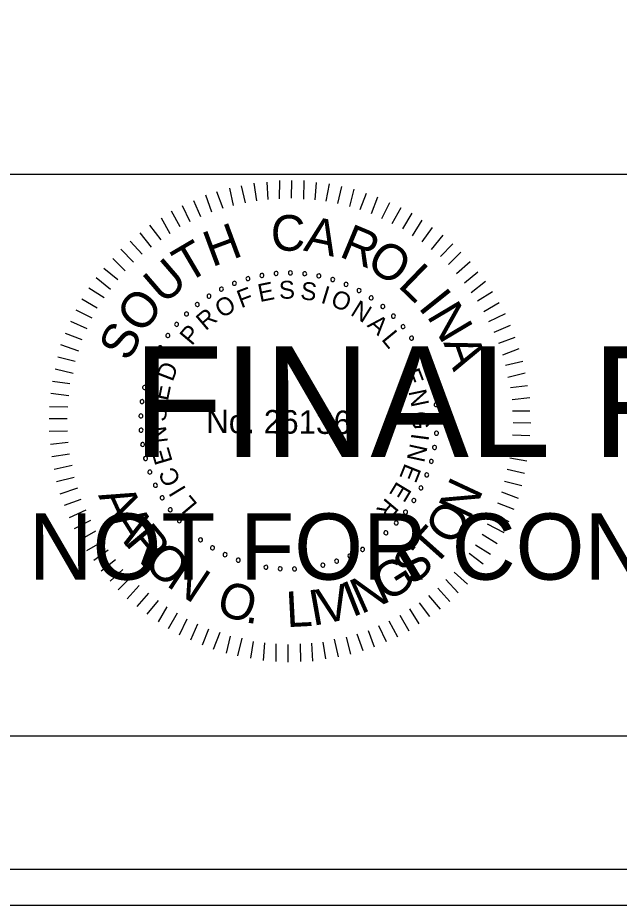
# Model space of a CAD drawing. Extents: x 967 to 1326, y 964 to 3704.
# Drawn here: x 1170.56 to 1189.3, y 963.72 to 991.36 of the extents above; entities that cross this region are included whole.
import ezdxf

# ---------------------------------------------------------------- set-up
doc = ezdxf.new("R2010")
doc.units = 0
for name, color, linetype in [('RD_SHT_Bndy', 7, 'Continuous'), ('RD_SHT_IplotShp', 7, 'Continuous'), ('RD_SHT_Misc1', 7, 'Continuous'), ('RD_SHT_Misc2', 7, 'Continuous'), ('RD_XS_TX_Station', 7, 'Continuous')]:
    doc.layers.add(name, color=color, linetype=linetype)

msp = doc.modelspace()

# ---------------------------------------------------------------- linework, layer by layer
at = {"layer": 'RD_SHT_Bndy'}
for p, q in [((996.114, 986.486), (1323.886, 986.486)), ((1323.886, 968.983), (996.114, 968.983))]:
    msp.add_line(p, q, dxfattribs=at)
at = {"layer": 'RD_SHT_IplotShp'}
for points in [[(967.409, 963.72), (1326.285, 963.72), (1326.285, 1183.72), (967.409, 1183.72)], [(988.525, 964.84), (1326.285, 964.84), (1326.285, 1182.6), (988.525, 1182.6)]]:
    msp.add_lwpolyline(points, close=True, dxfattribs=at)
at = {"layer": 'RD_SHT_Misc1'}
for p, q in [((1178.01, 985.663), (1177.93, 986.209)), ((1178.364, 985.699), (1178.33, 986.244)), ((1178.717, 985.719), (1178.722, 986.295)), ((1179.093, 985.739), (1179.098, 986.292)), ((1179.469, 985.713), (1179.489, 986.288)), ((1179.829, 985.687), (1179.872, 986.231)), ((1180.174, 985.646), (1180.271, 986.19)), ((1176.964, 985.419), (1176.769, 985.935)), ((1177.287, 985.508), (1177.169, 986.054)), ((1177.657, 985.597), (1177.53, 986.128)), ((1180.535, 985.573), (1180.662, 986.102)), ((1180.902, 985.478), (1181.045, 986.022)), ((1176.264, 985.156), (1176.053, 985.657)), ((1176.61, 985.306), (1176.423, 985.83)), ((1181.231, 985.384), (1181.428, 985.896)), ((1181.584, 985.265), (1181.78, 985.786)), ((1175.933, 985.005), (1175.699, 985.506)), ((1181.905, 985.109), (1182.154, 985.606)), ((1182.226, 984.953), (1182.506, 985.45)), ((1175.308, 984.634), (1175.036, 985.12)), ((1175.624, 984.846), (1175.352, 985.332)), ((1182.562, 984.789), (1182.85, 985.27)), ((1175.03, 984.445), (1174.681, 984.9)), ((1182.86, 984.572), (1183.163, 985.053)), ((1183.158, 984.378), (1183.484, 984.828)), ((1174.729, 984.217), (1174.372, 984.665)), ((1183.447, 984.145), (1183.811, 984.587)), ((1174.435, 983.997), (1174.062, 984.399)), ((1183.729, 983.92), (1184.116, 984.316)), ((1174.172, 983.753), (1173.776, 984.148)), ((1183.98, 983.672), (1184.368, 984.061)), ((1173.909, 983.479), (1173.52, 983.858)), ((1184.232, 983.394), (1184.657, 983.767)), ((1173.684, 983.197), (1173.242, 983.546)), ((1184.475, 983.108), (1184.892, 983.45)), ((1173.451, 982.9), (1173.009, 983.256)), ((1184.687, 982.807), (1185.128, 983.156)), ((1173.257, 982.64), (1172.776, 982.936)), ((1173.039, 982.312), (1172.559, 982.6)), ((1184.885, 982.544), (1185.355, 982.832)), ((1185.081, 982.213), (1185.56, 982.493)), ((1172.883, 982.006), (1172.379, 982.256)), ((1185.24, 981.904), (1185.756, 982.145)), ((1172.727, 981.677), (1172.215, 981.904)), ((1185.399, 981.573), (1185.907, 981.791)), ((1172.571, 981.333), (1172.051, 981.53)), ((1185.549, 981.226), (1186.057, 981.414)), ((1172.461, 980.974), (1171.91, 981.178)), ((1185.669, 980.865), (1186.185, 981.06)), ((1172.351, 980.652), (1171.807, 980.787)), ((1185.759, 980.541), (1186.297, 980.667)), ((1172.286, 980.276), (1171.727, 980.419)), ((1185.832, 980.165), (1186.371, 980.298)), ((1172.191, 979.955), (1171.647, 980.029)), ((1185.906, 979.842), (1186.436, 979.906)), ((1172.15, 979.587), (1171.598, 979.653)), ((1185.964, 979.473), (1186.51, 979.53)), ((1172.124, 979.234), (1171.548, 979.239)), ((1185.977, 979.12), (1186.514, 979.115)), ((1172.105, 978.866), (1171.545, 978.871)), ((1185.997, 978.751), (1186.542, 978.747)), ((1172.118, 978.482), (1171.542, 978.471)), ((1185.971, 978.368), (1186.508, 978.348)), ((1172.138, 978.136), (1171.585, 978.072)), ((1185.952, 978.022), (1186.497, 977.949)), ((1172.173, 977.768), (1171.627, 977.688)), ((1185.888, 977.655), (1186.417, 977.566)), ((1172.262, 977.414), (1171.701, 977.296)), ((1185.808, 977.302), (1186.345, 977.175)), ((1172.321, 977.037), (1171.774, 976.911)), ((1185.729, 976.926), (1186.265, 976.792)), ((1172.425, 976.707), (1171.871, 976.519)), ((1185.634, 976.597), (1186.146, 976.401)), ((1172.53, 976.36), (1172.007, 976.173)), ((1185.508, 976.253), (1186.013, 976.057)), ((1172.681, 976.029), (1172.165, 975.788)), ((1172.831, 975.705), (1172.323, 975.441)), ((1185.352, 975.924), (1185.857, 975.675)), ((1185.188, 975.603), (1185.7, 975.33)), ((1172.982, 975.374), (1172.497, 975.094)), ((1185.024, 975.274), (1185.498, 974.987)), ((1173.194, 975.042), (1172.709, 974.762)), ((1184.822, 974.946), (1185.288, 974.658)), ((1173.384, 974.78), (1172.936, 974.453)), ((1184.62, 974.687), (1185.055, 974.353)), ((1173.612, 974.478), (1173.164, 974.129)), ((1184.403, 974.389), (1184.814, 974.033)), ((1173.832, 974.177), (1173.437, 973.812)), ((1184.155, 974.092), (1184.574, 973.72)), ((1174.091, 973.945), (1173.689, 973.541)), ((1183.899, 973.864), (1184.28, 973.454)), ((1174.35, 973.674), (1173.97, 973.263)), ((1183.644, 973.597), (1184.024, 973.18)), ((1174.64, 973.442), (1174.275, 973.022)), ((1174.937, 973.209), (1174.58, 972.782)), ((1183.358, 973.37), (1183.715, 972.944)), ((1175.212, 973.014), (1174.932, 972.549)), ((1182.764, 972.952), (1183.059, 972.482)), ((1183.065, 973.141), (1183.384, 972.709)), ((1175.525, 972.812), (1175.245, 972.331)), ((1182.463, 972.755), (1182.743, 972.269)), ((1175.83, 972.633), (1175.588, 972.136)), ((1176.159, 972.477), (1175.94, 971.98)), ((1181.8, 972.431), (1182.041, 971.93)), ((1182.124, 972.581), (1182.396, 972.08)), ((1176.503, 972.321), (1176.307, 971.816)), ((1176.855, 972.211), (1176.651, 971.69)), ((1177.177, 972.1), (1177.05, 971.572)), ((1181.122, 972.175), (1181.31, 971.652)), ((1181.476, 972.28), (1181.664, 971.771)), ((1177.545, 972.036), (1177.409, 971.484)), ((1177.897, 971.933), (1177.808, 971.412)), ((1178.25, 971.892), (1178.207, 971.34)), ((1178.603, 971.866), (1178.598, 971.313)), ((1178.978, 971.84), (1178.974, 971.295)), ((1179.355, 971.86), (1179.365, 971.307)), ((1179.715, 971.88), (1179.749, 971.327)), ((1180.061, 971.915), (1180.149, 971.393)), ((1180.423, 972.012), (1180.541, 971.458)), ((1180.791, 972.07), (1180.926, 971.54))]:
    msp.add_line(p, q, dxfattribs=at)
for centre, start, end in [((1178.609, 983.397), 5.0653, 185.0653), ((1179.055, 983.414), 359.5268, 179.5268), ((1179.5, 983.388), 353.9884, 173.9884), ((1177.312, 983.091), 21.6807, 201.6807), ((1177.734, 983.235), 16.1422, 196.1422), ((1177.734, 983.235), 196.1422, 16.1422), ((1178.168, 983.337), 10.6038, 190.6038), ((1178.168, 983.337), 190.6038, 10.6038), ((1178.609, 983.397), 185.0653, 5.0653), ((1179.055, 983.414), 179.5268, 359.5268), ((1179.5, 983.388), 173.9884, 353.9884), ((1179.94, 983.319), 168.4499, 348.4499), ((1179.94, 983.319), 348.4499, 168.4499), ((1180.372, 983.208), 162.9114, 342.9114), ((1180.372, 983.208), 342.9114, 162.9114), ((1176.906, 982.908), 27.2191, 207.2191), ((1176.906, 982.908), 207.2191, 27.2191), ((1177.312, 983.091), 201.6807, 21.6807), ((1180.79, 983.056), 157.373, 337.373), ((1180.79, 983.056), 337.373, 157.373), ((1181.193, 982.864), 151.8345, 331.8345), ((1181.193, 982.864), 331.8345, 151.8345), ((1176.52, 982.686), 32.7576, 212.7576), ((1176.52, 982.686), 212.7576, 32.7576), ((1181.574, 982.634), 146.2961, 326.2961), ((1181.574, 982.634), 326.2961, 146.2961), ((1176.156, 982.428), 38.2961, 218.2961), ((1176.156, 982.428), 218.2961, 38.2961), ((1181.932, 982.368), 140.7576, 320.7576), ((1181.932, 982.368), 320.7576, 140.7576), ((1175.82, 982.135), 43.8345, 223.8345), ((1175.82, 982.135), 223.8345, 43.8345), ((1182.263, 982.069), 135.2191, 315.2191), ((1182.263, 982.069), 315.2191, 135.2191), ((1175.513, 981.812), 49.373, 229.373), ((1175.513, 981.812), 229.373, 49.373), ((1182.563, 981.74), 129.6807, 309.6807), ((1182.563, 981.74), 309.6807, 129.6807), ((1175.239, 981.461), 54.9114, 234.9114), ((1175.239, 981.461), 234.9114, 54.9114), ((1182.83, 981.383), 124.1422, 304.1422), ((1182.83, 981.383), 304.1422, 124.1422), ((1175, 981.085), 60.4499, 240.4499), ((1175, 981.085), 240.4499, 60.4499), ((1183.061, 981.002), 118.6038, 298.6038), ((1183.061, 981.002), 298.6038, 118.6038), ((1174.798, 980.687), 65.9884, 245.9884), ((1174.798, 980.687), 245.9884, 65.9884), ((1183.255, 980.601), 293.0653, 113.0653), ((1183.255, 980.601), 113.0653, 293.0653), ((1174.636, 980.272), 71.5268, 251.5268), ((1174.636, 980.272), 251.5268, 71.5268), ((1183.408, 980.182), 107.5268, 287.5268), ((1183.408, 980.182), 287.5268, 107.5268), ((1174.514, 979.843), 77.0653, 257.0653), ((1174.514, 979.843), 257.0653, 77.0653), ((1183.521, 979.751), 101.9884, 281.9884), ((1183.521, 979.751), 281.9884, 101.9884), ((1174.435, 979.405), 82.6038, 262.6038), ((1174.435, 979.405), 262.6038, 82.6038), ((1183.592, 979.311), 96.4499, 276.4499), ((1183.592, 979.311), 276.4499, 96.4499), ((1174.398, 978.961), 88.1422, 268.1422), ((1174.398, 978.961), 268.1422, 88.1422), ((1183.619, 978.866), 90.9114, 270.9114), ((1183.619, 978.866), 270.9114, 90.9114), ((1174.404, 978.515), 93.6807, 273.6807), ((1174.404, 978.515), 273.6807, 93.6807), ((1183.604, 978.421), 85.373, 265.373), ((1183.604, 978.421), 265.373, 85.373), ((1174.453, 978.072), 99.2191, 279.2191), ((1174.453, 978.072), 279.2191, 99.2191), ((1183.546, 977.979), 79.8345, 259.8345), ((1183.546, 977.979), 259.8345, 79.8345), ((1174.545, 977.636), 104.7576, 284.7576), ((1174.545, 977.636), 284.7576, 104.7576), ((1183.445, 977.545), 74.2961, 254.2961), ((1183.445, 977.545), 254.2961, 74.2961), ((1174.678, 977.211), 110.2961, 290.2961), ((1174.678, 977.211), 290.2961, 110.2961), ((1183.303, 977.122), 68.7576, 248.7576), ((1183.303, 977.122), 248.7576, 68.7576), ((1174.852, 976.8), 115.8345, 295.8345), ((1174.852, 976.8), 295.8345, 115.8345), ((1183.121, 976.716), 63.2191, 243.2191), ((1183.121, 976.716), 243.2191, 63.2191), ((1175.065, 976.409), 121.373, 301.373), ((1175.065, 976.409), 301.373, 121.373), ((1182.9, 976.328), 57.6807, 237.6807), ((1182.9, 976.328), 237.6807, 57.6807), ((1175.314, 976.039), 126.9114, 306.9114), ((1175.314, 976.039), 306.9114, 126.9114), ((1182.643, 975.964), 52.1422, 232.1422), ((1182.643, 975.964), 232.1422, 52.1422), ((1175.598, 975.696), 132.4499, 312.4499), ((1175.598, 975.696), 312.4499, 132.4499), ((1182.353, 975.627), 46.6038, 226.6038), ((1175.914, 975.381), 137.9884, 317.9884), ((1175.914, 975.381), 317.9884, 137.9884), ((1182.353, 975.627), 226.6038, 46.6038), ((1176.258, 975.099), 143.5268, 323.5268), ((1176.258, 975.099), 323.5268, 143.5268), ((1182.03, 975.319), 41.0653, 221.0653), ((1182.03, 975.319), 221.0653, 41.0653), ((1176.629, 974.851), 149.0653, 329.0653), ((1176.629, 974.851), 329.0653, 149.0653), ((1181.305, 974.803), 29.9884, 209.9884), ((1181.68, 975.043), 35.5268, 215.5268), ((1181.68, 975.043), 215.5268, 35.5268), ((1177.021, 974.639), 154.6038, 334.6038), ((1177.021, 974.639), 334.6038, 154.6038), ((1180.908, 974.6), 24.4499, 204.4499), ((1180.908, 974.6), 204.4499, 24.4499), ((1181.305, 974.803), 209.9884, 29.9884), ((1177.432, 974.467), 160.1422, 340.1422), ((1177.432, 974.467), 340.1422, 160.1422), ((1177.858, 974.335), 165.6807, 345.6807), ((1177.858, 974.335), 345.6807, 165.6807), ((1178.294, 974.245), 351.2191, 171.2191), ((1180.065, 974.313), 13.373, 193.373), ((1180.065, 974.313), 193.373, 13.373), ((1180.494, 974.436), 18.9114, 198.9114), ((1180.494, 974.436), 198.9114, 18.9114), ((1178.294, 974.245), 171.2191, 351.2191), ((1178.737, 974.198), 356.7576, 176.7576), ((1178.737, 974.198), 176.7576, 356.7576), ((1179.183, 974.193), 2.2961, 182.2961), ((1179.183, 974.193), 182.2961, 2.2961), ((1179.627, 974.232), 7.8345, 187.8345), ((1179.627, 974.232), 187.8345, 7.8345)]:
    msp.add_arc(centre, 0.0627, start, end, dxfattribs=at)
at = {"layer": 'RD_XS_TX_Station'}
msp.add_lwpolyline([(967.409, 963.72), (1326.285, 963.72), (1326.285, 1183.72), (967.409, 1183.72)], close=True, dxfattribs=at)

# ---------------------------------------------------------------- texts
at = {"layer": 'RD_SHT_Misc1'}
for s, height, rotation, p in [('C', 1.11, 359.5482, (1178.442, 984.108)), ('A', 1.11, 348.1981, (1179.439, 984.115)), ('H', 1.11, 20.3637, (1176.614, 983.587)), ('R', 1.11, 337.4344, (1180.541, 983.937)), ('T', 1.11, 30.4992, (1175.828, 983.072)), ('O', 1.108, 326.5869, (1181.366, 983.609)), ('U', 1.11, 40.8022, (1175.102, 982.403)), ('L', 1.11, 315.9488, (1182.373, 983.003)), ('S', 0.557, 2.208, (1178.709, 982.601)), ('F', 0.557, 20.6127, (1177.52, 982.309)), ('E', 0.557, 11.4103, (1178.103, 982.503)), ('S', 0.557, 352.6608, (1179.346, 982.599)), ('I', 0.557, 343.1136, (1179.975, 982.491)), ('I', 1.11, 308.6613, (1183.011, 982.338)), ('O', 1.11, 52.0267, (1174.435, 981.474)), ('O', 0.557, 30.8477, (1176.917, 981.987)), ('O', 0.557, 338.4392, (1180.274, 982.401)), ('N', 0.557, 328.2042, (1180.896, 982.12)), ('N', 1.11, 300.7037, (1183.285, 982.075)), ('R', 0.557, 40.3949, (1176.415, 981.594)), ('A', 0.557, 318.657, (1181.424, 981.762)), ('S', 1.108, 63.2511, (1174.029, 980.619)), ('P', 0.557, 49.9421, (1175.985, 981.124)), ('L', 0.557, 309.4546, (1181.869, 981.339)), ('A', 1.11, 289.4792, (1183.814, 981.243)), ('D', 0.557, 69.0364, (1175.386, 980.003)), ('E', 0.557, 291.049, (1182.53, 980.307)), ('E', 0.557, 78.2388, (1175.238, 979.407)), ('N', 0.557, 281.8466, (1182.728, 979.726)), ('S', 0.557, 87.786, (1175.187, 978.772)), ('No. 26136', 0.7311, 359.5268, (1176.429, 978.43)), ('G', 0.557, 272.2995, (1182.833, 979.097)), ('N', 0.557, 97.3332, (1175.242, 978.137)), ('I', 0.557, 262.4084, (1182.83, 978.437)), ('E', 0.557, 106.5355, (1175.394, 977.541)), ('N', 0.557, 257.7339, (1182.789, 978.127)), ('E', 0.557, 248.1867, (1182.628, 977.511)), ('C', 0.557, 116.4266, (1175.661, 976.938)), ('E', 0.557, 238.9844, (1182.378, 976.949)), ('N', 1.105, 64.8922, (1184.632, 975.684)), ('A', 1.105, 294.7297, (1173.062, 976.486)), ('I', 0.557, 121.1011, (1175.823, 976.67)), ('L', 0.557, 129.9595, (1176.187, 976.204)), ('R', 0.557, 229.782, (1182.041, 976.435)), ('O', 1.105, 56.2059, (1184.102, 974.874)), ('A', 1.105, 302.2892, (1173.414, 975.72)), ('R', 1.105, 309.8487, (1173.865, 975.007)), ('T', 1.105, 48.2685, (1183.515, 974.211)), ('O', 1.105, 317.7861, (1174.434, 974.33)), ('S', 1.105, 40.3311, (1182.842, 973.636)), ('N', 1.105, 326.4725, (1175.158, 973.686)), ('G', 1.105, 32.0198, (1182.059, 973.14)), ('N', 1.105, 24.0824, (1181.252, 972.776)), ('O', 1.105, 342.3472, (1176.697, 972.82)), ('V', 1.105, 12.7741, (1180.033, 972.457)), ('I', 1.105, 21.4605, (1180.976, 972.681)), ('L', 1.105, 2.9677, (1178.943, 972.379)), ('I', 1.105, 10.1523, (1179.743, 972.418)), ('.', 1.105, 351.0336, (1177.623, 972.536))]:
    msp.add_text(s, height=height, rotation=rotation, dxfattribs=at).set_placement(p)
at = {"layer": 'RD_SHT_Misc2'}
for s, height, p in [('FINAL PLANS', 3.4375, (1174.145, 977.685)), ('NOT FOR CONSTRUCTION', 2.0625, (1170.901, 973.86))]:
    msp.add_text(s, height=height, dxfattribs=at).set_placement(p)

doc.saveas('drawing.dxf')
